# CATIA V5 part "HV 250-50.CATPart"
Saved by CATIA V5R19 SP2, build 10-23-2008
Part number: HV 250-50
Bounding box of the stored display mesh (mm): x -18.951 to 18.951, y -18.952 to 18.952, z 0.053 to 169
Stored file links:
  C:\Users\Bora\Desktop\3D KATI MODEL- CATIA PART\HV serisi\HV 250\HV 250-50.CATPart
  C:\Program Files\Dassault Systemes\B19\intel_a\reffiles\standard\MetricThickPitch.txt
  C:\Program Files\Dassault Systemes\B19\intel_a\reffiles\standard\MetricThinPitch.txt
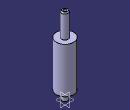
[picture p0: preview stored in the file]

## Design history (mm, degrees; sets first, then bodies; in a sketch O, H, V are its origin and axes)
Body1 (main body)
  Sketch1 on yz-plane, origin (0, 0, 0), H (0, 1, 0), V (0, 0, 1)
    point P1 (7.5, 167)
    point P3 (7.5, 167)
    point P7 (6, 17)
    point P8 (6, 1)
    point P10 (6, 1)
    point P12 (6, 17)
    line L1 (7.5, 167) -> (7.5, 118)
    arc A1 centre (5.5, 167) radius 2 from (7.5, 167) to (5.5, 169) ccw
    line L2 (6, 17) -> (6, 1)
    line L3 (5, 0) -> (6, 1)
    arc A2 centre (6, 18) radius 1 from (6, 19) to (6, 17) ccw
    line L4 (0, 0) -> (5, 0)
    line L5 (6, 19) -> (19, 19)
    line L6 (7.5, 118) -> (19, 118)
    line L7 (5.5, 169) -> (0, 169)
    point P13 (0, 169)
    line L8 (19, 118) -> (19, 19)
    horizontal: L4 H, L5 H, L6 H
    coincidence: P13 V, P1 P3, P7 P12, P8 P10
    tangency: L7 A1
    vertical: L8 V
  Shaft1: profile Sketch1, axis Sketch1.V, angle 360
  Sketch2 on face of Shaft1 from Sketch1.L4, origin (0, 0, 0), H (1, 0, 0), V (0, -1, 0)
    point P1 (0, 0)
  Hole1: placed by Sketch2, at (0, 0, 0) direction (0, 0, 1), diameter 10.106, depth 19, threaded "M12", thread diameter 12, thread depth 19, pitch 1.75
  Sketch3 on face of Shaft1 from Sketch1.L7, origin (0, 0, 169), H (1, 0, 0), V (0, 1, 0)
    point P1 (0, 0)
  Hole2: placed by Sketch3, at (0, 0, 169) direction (0, 0, -1), diameter 6.647, depth 15, threaded "M8", thread diameter 8, thread depth 15, pitch 1.25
